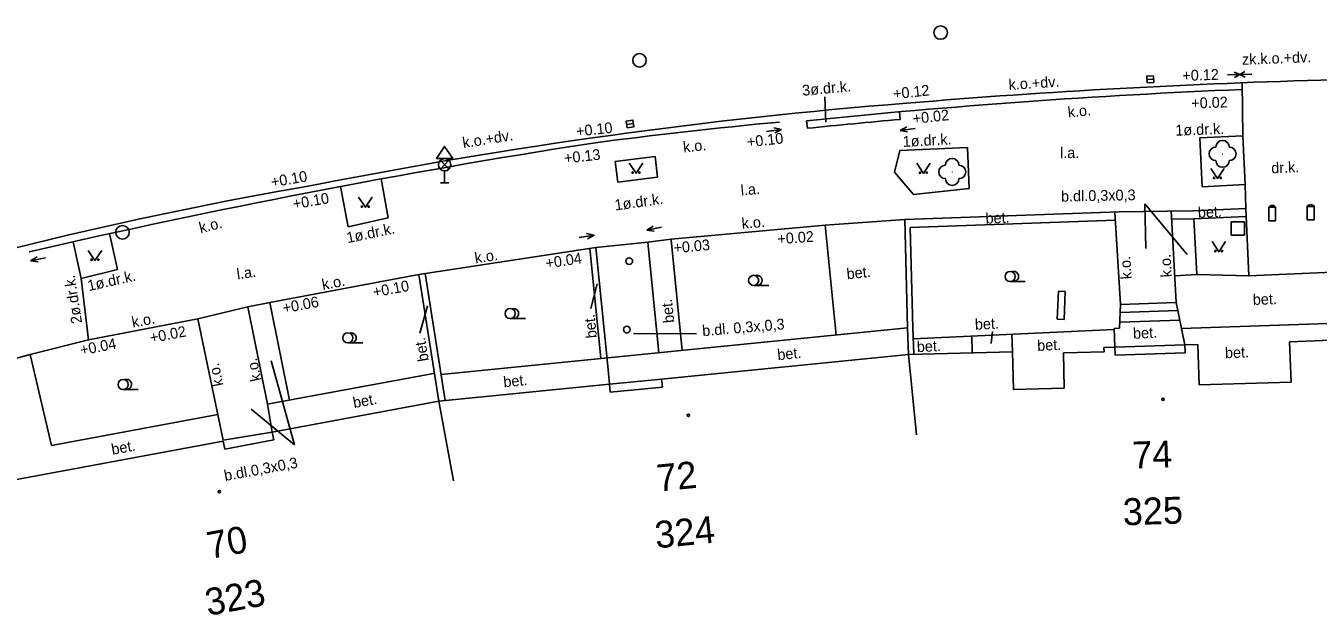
# Model space of a CAD drawing. Extents: x -597862 to -597276, y -1159156 to -1158889.
# Drawn here: x -597770.58 to -597722.63, y -1159095.96 to -1159074.09 of the extents above; entities that cross this region are included whole.
import ezdxf

# ---------------------------------------------------------------- set-up
doc = ezdxf.new("R2010")
doc.units = 0
for name, color, linetype in [('Vrstva 12', 7, 'Continuous'), ('Vrstva 14', 7, 'Continuous'), ('Vrstva 15', 7, 'Continuous'), ('Vrstva 23', 7, 'Continuous'), ('Vrstva 24', 7, 'Continuous'), ('Vrstva 25', 7, 'Continuous'), ('Vrstva 26', 7, 'Continuous'), ('Vrstva 29', 7, 'Continuous'), ('Vrstva 4', 7, 'Continuous'), ('Vrstva 43', 7, 'Continuous'), ('Vrstva 44', 7, 'Continuous'), ('Vrstva 49', 7, 'Continuous'), ('Vrstva 5', 7, 'Continuous'), ('Vrstva 50', 7, 'Continuous'), ('Vrstva 7', 7, 'Continuous')]:
    doc.layers.add(name, color=color, linetype=linetype)

msp = doc.modelspace()

# ---------------------------------------------------------------- linework, layer by layer
at = {"layer": 'Vrstva 12'}
for p, q in [((-597730.004, -1159085.309), (-597729.97, -1159084.43)), ((-597727.9, -1159084.36), (-597727.579, -1159085.927)), ((-597730.204, -1159085.316), (-597730.004, -1159085.309)), ((-597730.18, -1159086.016), (-597730.204, -1159085.316))]:
    msp.add_line(p, q, dxfattribs=at)
at = {"layer": 'Vrstva 14'}
for p, q in [((-597743.576, -1159083.721), (-597743.014, -1159083.721)), ((-597734.059, -1159083.576), (-597733.497, -1159083.576)), ((-597752.607, -1159084.954), (-597752.045, -1159084.954)), ((-597758.631, -1159085.857), (-597758.069, -1159085.857)), ((-597766.967, -1159087.584), (-597766.405, -1159087.584))]:
    msp.add_line(p, q, dxfattribs=at)
for points in [[(-597748.19, -1159079.184), (-597747.94, -1159079.559), (-597747.69, -1159079.184)], [(-597737.526, -1159079.19), (-597737.276, -1159079.565), (-597737.026, -1159079.19)], [(-597726.62, -1159079.384), (-597726.37, -1159079.759), (-597726.12, -1159079.384)], [(-597758.232, -1159080.445), (-597757.982, -1159080.82), (-597757.732, -1159080.445)], [(-597726.571, -1159082.098), (-597726.321, -1159082.473), (-597726.071, -1159082.098)], [(-597768.263, -1159082.421), (-597768.013, -1159082.796), (-597767.763, -1159082.421)]]:
    msp.add_lwpolyline(points, dxfattribs=at)
for centre, radius in [((-597726.18, -1159078.84), 0.00025), ((-597748.065, -1159079.534), 0.025), ((-597747.815, -1159079.534), 0.025), ((-597737.401, -1159079.54), 0.025), ((-597737.151, -1159079.54), 0.025), ((-597736.21, -1159079.51), 0.00025), ((-597726.495, -1159079.734), 0.025), ((-597726.245, -1159079.734), 0.025), ((-597758.107, -1159080.795), 0.025), ((-597757.857, -1159080.795), 0.025), ((-597726.446, -1159082.448), 0.025), ((-597726.196, -1159082.448), 0.025), ((-597768.138, -1159082.771), 0.025), ((-597767.888, -1159082.771), 0.025), ((-597743.576, -1159083.533), 0.188), ((-597734.059, -1159083.388), 0.188), ((-597752.607, -1159084.766), 0.188), ((-597758.631, -1159085.669), 0.188), ((-597766.967, -1159087.396), 0.188)]:
    msp.add_circle(centre, radius, dxfattribs=at)
for centre, radius, start, end in [((-597726.43, -1159078.84), 0.25, 90, 270), ((-597726.18, -1159078.59), 0.25, 0, 180), ((-597725.93, -1159078.84), 0.25, 270, 90), ((-597736.21, -1159079.26), 0.25, 0, 180), ((-597726.18, -1159079.09), 0.25, 180, 360), ((-597736.46, -1159079.51), 0.25, 90, 270), ((-597735.96, -1159079.51), 0.25, 270, 90), ((-597736.21, -1159079.76), 0.25, 180, 360), ((-597743.451, -1159083.533), 0.188, 249.4944, 109.0474), ((-597733.934, -1159083.388), 0.188, 249.4944, 109.0474), ((-597752.482, -1159084.766), 0.188, 249.4944, 109.0474), ((-597758.506, -1159085.669), 0.188, 249.4944, 109.0474), ((-597766.842, -1159087.396), 0.188, 249.4944, 109.0474)]:
    msp.add_arc(centre, radius, start, end, dxfattribs=at)
at = {"layer": 'Vrstva 15'}
for points in [[(-597729.97, -1159084.43), (-597727.9, -1159084.36)], [(-597729.982, -1159084.731), (-597727.839, -1159084.658)], [(-597729.996, -1159085.09), (-597727.766, -1159085.014)]]:
    msp.add_lwpolyline(points, dxfattribs=at)
for centre in [(-597728.393, -1159087.951), (-597745.995, -1159088.542), (-597763.396, -1159091.371)]:
    msp.add_circle(centre, 0.0438, dxfattribs=at)
at = {"layer": 'Vrstva 23'}
for p, q in [((-597725.36, -1159081.36), (-597725.86, -1159081.36)), ((-597725.86, -1159081.36), (-597725.86, -1159081.86)), ((-597725.36, -1159081.86), (-597725.36, -1159081.36)), ((-597725.86, -1159081.86), (-597725.36, -1159081.86))]:
    msp.add_line(p, q, dxfattribs=at)
at = {"layer": 'Vrstva 24'}
msp.add_circle((-597748.19, -1159082.82), 0.125, dxfattribs=at)
at = {"layer": 'Vrstva 25'}
for p, q in [((-597728.985, -1159076.076), (-597728.735, -1159076.064)), ((-597748.284, -1159077.747), (-597748.036, -1159077.713))]:
    msp.add_line(p, q, dxfattribs=at)
for points in [[(-597728.978, -1159076.201), (-597728.729, -1159076.188), (-597728.742, -1159075.939), (-597728.991, -1159075.952)], [(-597748.267, -1159077.871), (-597748.019, -1159077.837), (-597748.053, -1159077.589), (-597748.301, -1159077.623)]]:
    msp.add_lwpolyline(points, close=True, dxfattribs=at)
for centre in [(-597736.64, -1159074.34), (-597747.81, -1159075.37), (-597766.99, -1159081.75)]:
    msp.add_circle(centre, 0.25, dxfattribs=at)
at = {"layer": 'Vrstva 26'}
msp.add_circle((-597748.28, -1159085.36), 0.125, dxfattribs=at)
at = {"layer": 'Vrstva 29'}
msp.add_lwpolyline([(-597732.06, -1159084.98), (-597732.02, -1159083.95), (-597732.27, -1159083.94), (-597732.311, -1159084.97)], close=True, dxfattribs=at)
at = {"layer": 'Vrstva 4'}
for p, q in [((-597730.18, -1159086.016), (-597727.579, -1159085.927)), ((-597727.579, -1159085.926), (-597727.1, -1159085.91)), ((-597727.568, -1159086.226), (-597727.579, -1159085.927)), ((-597727.05, -1159087.409), (-597727.1, -1159085.91)), ((-597723.69, -1159085.81), (-597719.78, -1159085.67)), ((-597723.636, -1159087.309), (-597723.69, -1159085.81)), ((-597746.993, -1159087.195), (-597737.83, -1159086.28)), ((-597737.83, -1159086.28), (-597733.97, -1159086.18)), ((-597737.532, -1159089.265), (-597737.83, -1159086.28)), ((-597733.934, -1159087.588), (-597733.97, -1159086.18)), ((-597730.575, -1159086.18), (-597732.085, -1159086.22)), ((-597732.085, -1159086.22), (-597732.051, -1159087.54)), ((-597730.58, -1159086.03), (-597730.18, -1159086.016)), ((-597730.575, -1159086.18), (-597730.58, -1159086.03)), ((-597730.18, -1159086.016), (-597730.169, -1159086.315)), ((-597755.26, -1159088.02), (-597748.923, -1159087.388)), ((-597748.923, -1159087.388), (-597746.993, -1159087.195)), ((-597748.923, -1159087.387), (-597748.893, -1159087.685)), ((-597746.993, -1159087.195), (-597746.963, -1159087.493)), ((-597727.05, -1159087.409), (-597723.636, -1159087.309)), ((-597732.051, -1159087.54), (-597733.934, -1159087.588)), ((-597761.436, -1159089.164), (-597755.26, -1159088.02)), ((-597754.714, -1159090.97), (-597755.26, -1159088.02)), ((-597763.26, -1159089.46), (-597761.436, -1159089.164)), ((-597761.436, -1159089.163), (-597761.381, -1159089.457)), ((-597772.44, -1159091.2), (-597763.253, -1159089.499)), ((-597763.198, -1159089.793), (-597763.253, -1159089.499))]:
    msp.add_line(p, q, dxfattribs=at)
at = {"layer": 'Vrstva 44'}
for p, q in [((-597754.89, -1159079.07), (-597755.19, -1159079.414)), ((-597755.19, -1159079.07), (-597754.89, -1159079.414)), ((-597755.04, -1159079.92), (-597755.04, -1159079.47)), ((-597755.19, -1159079.92), (-597754.89, -1159079.92))]:
    msp.add_line(p, q, dxfattribs=at)
msp.add_lwpolyline([(-597755.34, -1159079.014), (-597754.74, -1159079.014), (-597755.04, -1159078.564), (-597755.34, -1159079.014)], dxfattribs=at)
for points in [[(-597724.465, -1159081.32), (-597724.215, -1159081.32), (-597724.215, -1159080.82), (-597724.465, -1159080.82)], [(-597723.035, -1159081.29), (-597722.785, -1159081.29), (-597722.785, -1159080.79), (-597723.035, -1159080.79)]]:
    msp.add_lwpolyline(points, close=True, dxfattribs=at)
msp.add_circle((-597755.04, -1159079.242), 0.228, dxfattribs=at)
for centre in [(-597724.34, -1159080.905), (-597722.91, -1159080.875)]:
    msp.add_arc(centre, 0.151, 34.3319, 145.6681, dxfattribs=at)
at = {"layer": 'Vrstva 49'}
for p, q in [((-597725.094, -1159075.88), (-597725.994, -1159075.912)), ((-597725.544, -1159075.896), (-597725.748, -1159075.806)), ((-597725.544, -1159075.896), (-597725.348, -1159075.789)), ((-597725.544, -1159075.896), (-597725.742, -1159076.002)), ((-597725.544, -1159075.896), (-597725.343, -1159075.989)), ((-597740.9, -1159077.659), (-597740.931, -1159076.721)), ((-597743.102, -1159078.01), (-597742.544, -1159077.934)), ((-597742.544, -1159077.934), (-597742.821, -1159077.876)), ((-597742.544, -1159077.934), (-597742.793, -1159078.066)), ((-597738.141, -1159077.968), (-597737.892, -1159077.837)), ((-597737.583, -1159077.894), (-597738.141, -1159077.968)), ((-597738.141, -1159077.968), (-597737.864, -1159078.027)), ((-597729.066, -1159080.7), (-597729.021, -1159082.351)), ((-597729.066, -1159080.7), (-597727.487, -1159082.576)), ((-597747.543, -1159081.671), (-597747.301, -1159081.526)), ((-597746.989, -1159081.566), (-597747.543, -1159081.671)), ((-597750.05, -1159081.94), (-597749.494, -1159081.852)), ((-597749.494, -1159081.852), (-597749.772, -1159081.801)), ((-597749.494, -1159081.852), (-597749.74, -1159081.989)), ((-597747.543, -1159081.671), (-597747.263, -1159081.714)), ((-597770.399, -1159082.804), (-597770.157, -1159082.659)), ((-597769.845, -1159082.699), (-597770.399, -1159082.804)), ((-597770.399, -1159082.804), (-597770.119, -1159082.847)), ((-597749.62, -1159084.576), (-597749.387, -1159083.668)), ((-597755.961, -1159085.489), (-597755.67, -1159084.485)), ((-597734.71, -1159085.426), (-597734.758, -1159085.871)), ((-597748.028, -1159085.511), (-597745.69, -1159085.512)), ((-597760.612, -1159089.638), (-597761.476, -1159086.517)), ((-597760.612, -1159089.638), (-597762.213, -1159088.315))]:
    msp.add_line(p, q, dxfattribs=at)
at = {"layer": 'Vrstva 5'}
for p, q in [((-597727.568, -1159086.226), (-597730.169, -1159086.315)), ((-597748.893, -1159087.685), (-597746.963, -1159087.493)), ((-597763.198, -1159089.793), (-597761.381, -1159089.457))]:
    msp.add_line(p, q, dxfattribs=at)
at = {"layer": 'Vrstva 7'}
for p, q in [((-597725.453, -1159076.201), (-597725.43, -1159078.17)), ((-597738.16, -1159077.28), (-597738.135, -1159077.56)), ((-597741.58, -1159077.89), (-597741.618, -1159077.612)), ((-597727.025, -1159078.249), (-597725.43, -1159078.17)), ((-597727.025, -1159078.249), (-597726.935, -1159080.059)), ((-597725.43, -1159078.17), (-597725.34, -1159079.98)), ((-597738.35, -1159079.52), (-597738.15, -1159078.72)), ((-597738.15, -1159078.72), (-597735.64, -1159078.61)), ((-597735.64, -1159078.61), (-597735.58, -1159080.12)), ((-597747.233, -1159078.944), (-597748.713, -1159079.124)), ((-597748.713, -1159079.124), (-597748.62, -1159079.89)), ((-597747.14, -1159079.71), (-597747.233, -1159078.944)), ((-597748.62, -1159079.89), (-597747.14, -1159079.71)), ((-597758.62, -1159081.55), (-597758.903, -1159080.051)), ((-597757.13, -1159081.22), (-597757.396, -1159079.771)), ((-597726.935, -1159080.059), (-597725.34, -1159079.973)), ((-597725.34, -1159079.98), (-597725.31, -1159080.87)), ((-597737.97, -1159081.28), (-597730.021, -1159080.995)), ((-597730.17, -1159081), (-597729.97, -1159084.43)), ((-597730.021, -1159080.995), (-597728.239, -1159080.961)), ((-597728.239, -1159080.961), (-597727.26, -1159080.95)), ((-597728.09, -1159080.96), (-597727.9, -1159084.36)), ((-597727.26, -1159080.95), (-597725.31, -1159080.87)), ((-597725.208, -1159083.368), (-597725.31, -1159080.87)), ((-597758.62, -1159081.55), (-597757.13, -1159081.22)), ((-597746.64, -1159082.01), (-597740.92, -1159081.49)), ((-597740.92, -1159081.49), (-597737.97, -1159081.28)), ((-597740.92, -1159081.49), (-597740.513, -1159085.563)), ((-597737.97, -1159081.28), (-597737.87, -1159085.3)), ((-597737.763, -1159081.573), (-597730.153, -1159081.3)), ((-597737.763, -1159081.573), (-597737.67, -1159085.293)), ((-597728.073, -1159081.259), (-597727.252, -1159081.25)), ((-597727.252, -1159081.25), (-597725.298, -1159081.17)), ((-597727.243, -1159081.25), (-597727.128, -1159083.315)), ((-597768.52, -1159083.46), (-597768.825, -1159082.101)), ((-597767.18, -1159083.13), (-597767.472, -1159081.8)), ((-597749.43, -1159082.31), (-597747.5, -1159082.12)), ((-597747.5, -1159082.12), (-597746.64, -1159082.01)), ((-597747.5, -1159082.12), (-597747.09, -1159086.22)), ((-597746.637, -1159082.033), (-597746.227, -1159086.134)), ((-597756, -1159083.32), (-597749.43, -1159082.31)), ((-597749.648, -1159082.343), (-597749.239, -1159086.435)), ((-597749.43, -1159082.31), (-597749.002, -1159086.591)), ((-597768.52, -1159083.46), (-597767.18, -1159083.13)), ((-597768.25, -1159085.74), (-597768.52, -1159083.46)), ((-597761.53, -1159084.35), (-597756, -1159083.32)), ((-597756, -1159083.32), (-597755.26, -1159088.02)), ((-597755.763, -1159083.284), (-597755.021, -1159087.996)), ((-597727.956, -1159083.361), (-597727.128, -1159083.314)), ((-597725.208, -1159083.368), (-597727.128, -1159083.314)), ((-597725.208, -1159083.368), (-597719.931, -1159083.14)), ((-597764.2, -1159084.96), (-597762.34, -1159084.51)), ((-597762.34, -1159084.51), (-597761.53, -1159084.35)), ((-597761.61, -1159088.13), (-597762.34, -1159084.51)), ((-597760.797, -1159087.979), (-597761.529, -1159084.35)), ((-597768.25, -1159085.74), (-597764.2, -1159084.96)), ((-597764.2, -1159084.96), (-597763.26, -1159089.46)), ((-597755.173, -1159087.028), (-597737.87, -1159085.299)), ((-597737.87, -1159085.3), (-597737.83, -1159086.28)), ((-597737.67, -1159085.293), (-597737.63, -1159086.275)), ((-597737.653, -1159085.702), (-597730.203, -1159085.353)), ((-597727.702, -1159085.326), (-597720.25, -1159085.059)), ((-597770.42, -1159086.28), (-597768.25, -1159085.74)), ((-597735.48, -1159085.6), (-597735.464, -1159086.219)), ((-597733.97, -1159086.18), (-597734, -1159085.531)), ((-597773.51, -1159087.12), (-597770.42, -1159086.28)), ((-597770.42, -1159086.28), (-597769.63, -1159089.66)), ((-597749.002, -1159086.591), (-597748.923, -1159087.387)), ((-597761.626, -1159088.133), (-597755.45, -1159086.989)), ((-597761.61, -1159088.13), (-597761.436, -1159089.164)), ((-597769.63, -1159089.66), (-597763.457, -1159088.517))]:
    msp.add_line(p, q, dxfattribs=at)
msp.add_lwpolyline([(-597735.58, -1159080.12), (-597737.65, -1159080.35), (-597738.35, -1159079.52)], dxfattribs=at)
for centre, radius, start, end in [((-597714.654, -1159355.996), 280.003, 91.51148, 94.7642), ((-597714.417, -1159343.13), 266.908, 92.36905, 95.84925), ((-597722.763, -1159267.35), 190.992, 94.5488, 101.17556), ((-597725.696, -1159259.024), 182.152, 95.33101, 97.54698), ((-597714.417, -1159343.13), 266.627, 95.10351, 95.84925), ((-597703.752, -1159372.098), 297.208, 98.87799, 102.96856), ((-597733.048, -1159235.075), 157.382, 99.77922, 107.63596)]:
    msp.add_arc(centre, radius, start, end, dxfattribs=at)

# ---------------------------------------------------------------- texts
at = {"layer": 'Vrstva 43'}
for s, rotation, p in [('74', 1.882, (-597729.514, -1159090.519)), ('72', 5.7008, (-597747.122, -1159091.374)), ('325', 1.882, (-597729.865, -1159092.627)), ('70', 10.4867, (-597763.753, -1159093.877)), ('324', 5.7008, (-597747.193, -1159093.482)), ('323', 10.4867, (-597763.824, -1159095.985))]:
    msp.add_text(s, height=1, rotation=rotation, dxfattribs=at).set_placement(p)
at = {"layer": 'Vrstva 49'}
for s, rotation, p in [('zk.k.o.+dv.', 2.1816, (-597725.453, -1159075.537)), ('3ø.dr.k.', 5.3035, (-597741.756, -1159076.686)), ('k.o.+dv.', 3.7721, (-597734.105, -1159076.471)), ('k.o.', 6.2804, (-597731.902, -1159077.496)), ('1ø.dr.k.', 2.1569, (-597727.924, -1159078.167)), ('k.o.+dv.', 8.9787, (-597754.344, -1159078.627)), ('1ø.dr.k.', 3.1296, (-597738.035, -1159078.584)), ('k.o.', 6.2804, (-597746.173, -1159078.792)), ('l.a.', 0.4195, (-597732.207, -1159079.001)), ('dr.k.', 2.4455, (-597724.365, -1159079.567)), ('l.a.', 5.1469, (-597744.038, -1159080.39)), ('b.dl.0,3x0,3', 1.1293, (-597732.168, -1159080.613)), ('1ø.dr.k.', 7.8971, (-597748.706, -1159080.941)), ('bet.', 2.6793, (-597734.965, -1159081.433)), ('bet.', 2.6793, (-597727.088, -1159081.215)), ('k.o.', 14.0916, (-597764.095, -1159081.786)), ('1ø.dr.k.', 11.7721, (-597758.634, -1159082.154)), ('k.o.', 4.8129, (-597744.005, -1159081.623)), ('k.o.', 8.7396, (-597753.895, -1159082.904)), ('k.o.', 93.3371, (-597728.062, -1159083.408)), ('l.a.', 8.3716, (-597762.723, -1159083.501)), ('bet.', 5.7044, (-597740.108, -1159083.494)), ('k.o.', 93.3371, (-597729.551, -1159083.482)), ('2ø.dr.k.', 98.9791, (-597768.488, -1159085.108)), ('1ø.dr.k.', 12.587, (-597768.239, -1159083.934)), ('k.o.', 10.5508, (-597759.556, -1159083.89)), ('bet.', 1.9942, (-597725.051, -1159084.446)), ('bet.', 95.7092, (-597746.52, -1159085.096)), ('k.o.', 10.9013, (-597766.607, -1159085.291)), ('bet.', 95.6847, (-597749.389, -1159085.661)), ('b.dl. 0,3x,0,3', 4.8827, (-597745.467, -1159085.607)), ('bet.', 2.6793, (-597735.36, -1159085.366)), ('bet.', 2.6793, (-597729.492, -1159085.702)), ('bet.', 99.2988, (-597755.629, -1159086.51)), ('bet.', 2.6793, (-597737.513, -1159086.198)), ('bet.', 2.6793, (-597733.048, -1159086.153)), ('bet.', 5.7044, (-597742.677, -1159086.497)), ('bet.', 1.9942, (-597726.083, -1159086.423)), ('k.o.', 101.7988, (-597763.246, -1159087.422)), ('k.o.', 101.7988, (-597761.836, -1159087.236)), ('bet.', 5.7044, (-597752.842, -1159087.504)), ('bet.', 10.4941, (-597758.401, -1159088.275)), ('bet.', 10.493, (-597767.364, -1159090.008)), ('b.dl.0,3x0,3', 10.4187, (-597763.185, -1159090.981))]:
    msp.add_text(s, height=0.4, rotation=rotation, dxfattribs=at).set_placement(p)
at = {"layer": 'Vrstva 50'}
for s, rotation, p in [('+0.12', 1.9464, (-597727.664, -1159076.136)), ('+0.12', 6.2451, (-597738.38, -1159076.815)), ('+0.02', 1.9464, (-597727.334, -1159077.16)), ('+0.02', 6.2451, (-597737.654, -1159077.733)), ('+0.10', 6.2451, (-597750.14, -1159078.203)), ('+0.10', 6.2451, (-597743.802, -1159078.597)), ('+0.13', 6.2451, (-597750.587, -1159079.199)), ('+0.10', 9.8607, (-597761.446, -1159080.086)), ('+0.10', 9.8607, (-597760.636, -1159080.898)), ('+0.03', 5.1944, (-597746.53, -1159082.528)), ('+0.02', 4.0718, (-597742.681, -1159082.195)), ('+0.04', 8.7396, (-597751.264, -1159083.1)), ('+0.10', 10.5508, (-597757.661, -1159084.166)), ('+0.06', 10.5508, (-597761.01, -1159084.759)), ('+0.02', 10.9013, (-597765.933, -1159085.864)), ('+0.04', 10.9013, (-597768.523, -1159086.318))]:
    msp.add_text(s, height=0.4, rotation=rotation, dxfattribs=at).set_placement(p)

doc.saveas('drawing.dxf')
